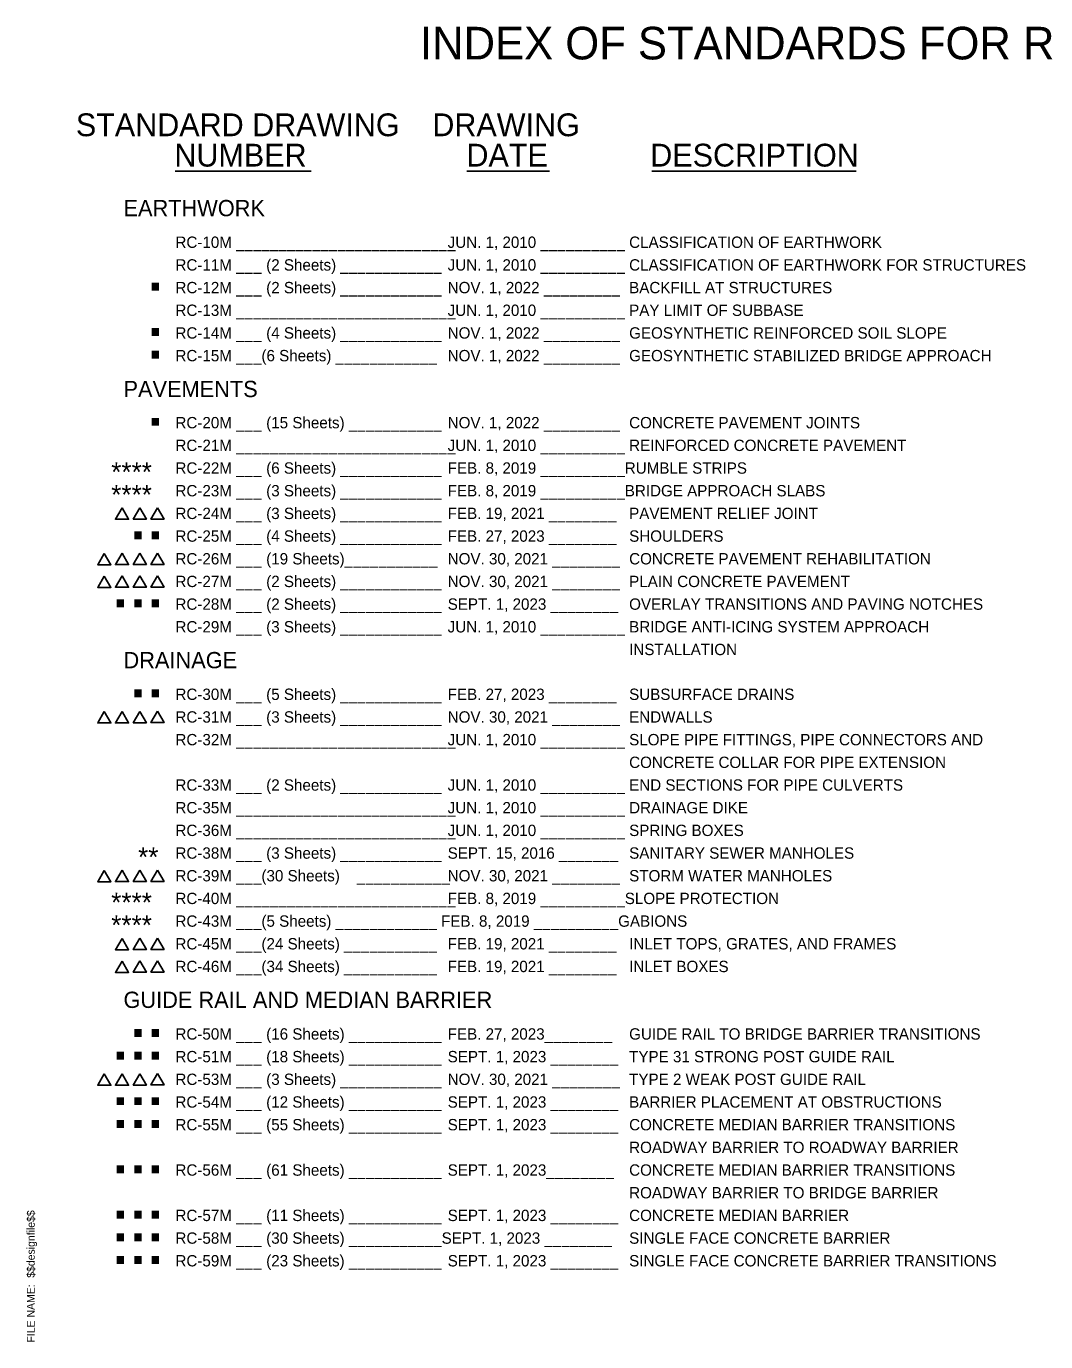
# Model space of a CAD drawing. Extents: x 0.08 to 2.68, y 0.04 to 1.72.
# Drawn here: x 0.084 to 1.387, y 0.043 to 1.725 of the extents above; entities that cross this region are included whole.
import ezdxf

# ---------------------------------------------------------------- set-up
doc = ezdxf.new("R2010")
doc.units = 0
doc.layers.add('Default', color=7, linetype='Continuous')
doc.layers.add('PLT-BNDY', color=7, linetype='Continuous')

msp = doc.modelspace()

# ---------------------------------------------------------------- linework, layer by layer
at = {"layer": 'PLT-BNDY'}
for p, q in [((0.2747, 1.5393), (0.4485, 1.5393)), ((0.6473, 1.5393), (0.7532, 1.5393)), ((0.8841, 1.5393), (1.1451, 1.5393))]:
    msp.add_line(p, q, dxfattribs=at)
for points in [[(0.2066, 1.1088), (0.1982, 1.0943), (0.215, 1.0943)], [(0.2293, 1.109), (0.2209, 1.0945), (0.2377, 1.0945)], [(0.252, 1.1091), (0.2436, 1.0946), (0.2604, 1.0946)], [(0.1839, 1.0507), (0.1755, 1.0362), (0.1923, 1.0362)], [(0.2066, 1.0508), (0.1982, 1.0363), (0.215, 1.0363)], [(0.2293, 1.051), (0.2209, 1.0365), (0.2377, 1.0365)], [(0.252, 1.0511), (0.2436, 1.0366), (0.2604, 1.0366)], [(0.1839, 1.0217), (0.1755, 1.0072), (0.1923, 1.0072)], [(0.2066, 1.0218), (0.1982, 1.0073), (0.215, 1.0073)], [(0.2293, 1.022), (0.2209, 1.0075), (0.2377, 1.0075)], [(0.252, 1.0221), (0.2436, 1.0076), (0.2604, 1.0076)], [(0.1839, 0.8484), (0.1755, 0.8339), (0.1923, 0.8339)], [(0.2066, 0.8485), (0.1982, 0.834), (0.215, 0.834)], [(0.2293, 0.8487), (0.2209, 0.8342), (0.2377, 0.8342)], [(0.252, 0.8488), (0.2436, 0.8343), (0.2604, 0.8343)], [(0.1839, 0.6454), (0.1755, 0.6309), (0.1923, 0.6309)], [(0.2066, 0.6455), (0.1982, 0.631), (0.215, 0.631)], [(0.2293, 0.6457), (0.2209, 0.6312), (0.2377, 0.6312)], [(0.252, 0.6458), (0.2436, 0.6313), (0.2604, 0.6313)], [(0.2066, 0.5585), (0.1982, 0.544), (0.215, 0.544)], [(0.2293, 0.5587), (0.2209, 0.5442), (0.2377, 0.5442)], [(0.252, 0.5588), (0.2436, 0.5443), (0.2604, 0.5443)], [(0.2066, 0.5295), (0.1982, 0.515), (0.215, 0.515)], [(0.2293, 0.5297), (0.2209, 0.5152), (0.2377, 0.5152)], [(0.252, 0.5298), (0.2436, 0.5153), (0.2604, 0.5153)], [(0.1839, 0.3851), (0.1755, 0.3706), (0.1923, 0.3706)], [(0.2066, 0.3852), (0.1982, 0.3707), (0.215, 0.3707)], [(0.2293, 0.3854), (0.2209, 0.3709), (0.2377, 0.3709)], [(0.252, 0.3855), (0.2436, 0.371), (0.2604, 0.371)]]:
    msp.add_lwpolyline(points, close=True, dxfattribs=at)

# ---------------------------------------------------------------- texts
at = {"layer": 'Default'}
for s, height, p in [('RC-10M __________________________', 0.0145, (0.2749, 1.4413)), ('JUN. 1, 2010 __________', 0.0145, (0.6229, 1.4413)), ('CLASSIFICATION OF EARTHWORK', 0.0145, (0.8549, 1.4413)), ('RC-11M ___', 0.0145, (0.2749, 1.4123)), ('(2 Sheets) ____________', 0.0145, (0.3909, 1.4123)), ('JUN. 1, 2010 __________', 0.0145, (0.6229, 1.4123)), ('CLASSIFICATION OF EARTHWORK FOR STRUCTURES', 0.0145, (0.8549, 1.4123)), ('■', 0.0145, (0.2434, 1.3853)), ('RC-12M ___', 0.0145, (0.2749, 1.3833)), ('(2 Sheets) ____________', 0.0145, (0.3909, 1.3833)), ('NOV. 1, 2022 _________', 0.0145, (0.6229, 1.3833)), ('BACKFILL AT STRUCTURES', 0.0145, (0.8549, 1.3833)), ('RC-13M __________________________', 0.0145, (0.2749, 1.3543)), ('JUN. 1, 2010 __________', 0.0145, (0.6229, 1.3543)), ('PAY LIMIT OF SUBBASE', 0.0145, (0.8549, 1.3543)), ('■', 0.0145, (0.2434, 1.3273)), ('RC-14M ___', 0.0145, (0.2749, 1.3253)), ('(4 Sheets) ____________', 0.0145, (0.3909, 1.3253)), ('NOV. 1, 2022 _________', 0.0145, (0.6229, 1.3253)), ('GEOSYNTHETIC REINFORCED SOIL SLOPE', 0.0145, (0.8549, 1.3253)), ('■', 0.0145, (0.2434, 1.2983)), ('RC-15M ___(6 Sheets) ____________', 0.0145, (0.2749, 1.2963)), ('NOV. 1, 2022 _________', 0.0145, (0.6229, 1.2963)), ('GEOSYNTHETIC STABILIZED BRIDGE APPROACH', 0.0145, (0.8549, 1.2963)), ('PAVEMENTS', 0.0208, (0.2085, 1.2505)), ('■', 0.0145, (0.2434, 1.2126)), ('■', 0.0145, (0.221, 1.0676)), ('■', 0.0145, (0.2434, 1.0676)), ('■', 0.0145, (0.1985, 0.9806)), ('■', 0.0145, (0.221, 0.9806)), ('■', 0.0145, (0.2434, 0.9806)), ('■', 0.0145, (0.221, 0.8653)), ('■', 0.0145, (0.2434, 0.8653)), ('RC-30M ___', 0.0145, (0.2749, 0.8633)), ('(5 Sheets) ____________', 0.0145, (0.3909, 0.8633)), ('FEB. 27, 2023 ________', 0.0145, (0.6229, 0.8633)), ('SUBSURFACE DRAINS', 0.0145, (0.8549, 0.8633)), ('RC-31M ___', 0.0145, (0.2749, 0.8343)), ('(3 Sheets) ____________', 0.0145, (0.3909, 0.8343)), ('NOV. 30, 2021 ________', 0.0145, (0.6229, 0.8343)), ('ENDWALLS', 0.0145, (0.8549, 0.8343)), ('RC-32M __________________________', 0.0145, (0.2749, 0.8053)), ('JUN. 1, 2010 __________', 0.0145, (0.6229, 0.8053)), ('SLOPE PIPE FITTINGS, PIPE CONNECTORS AND', 0.0145, (0.8549, 0.8053)), ('CONCRETE COLLAR FOR PIPE EXTENSION', 0.0145, (0.8549, 0.7763)), ('RC-33M ___', 0.0145, (0.2749, 0.7473)), ('(2 Sheets) ____________', 0.0145, (0.3909, 0.7473)), ('JUN. 1, 2010 __________', 0.0145, (0.6229, 0.7473)), ('END SECTIONS FOR PIPE CULVERTS', 0.0145, (0.8549, 0.7473)), ('RC-35M __________________________', 0.0145, (0.2749, 0.7183)), ('JUN. 1, 2010 __________', 0.0145, (0.6229, 0.7183)), ('DRAINAGE DIKE', 0.0145, (0.8549, 0.7183)), ('RC-36M __________________________', 0.0145, (0.2749, 0.6893)), ('JUN. 1, 2010 __________', 0.0145, (0.6229, 0.6893)), ('SPRING BOXES', 0.0145, (0.8549, 0.6893)), ('RC-38M ___', 0.0145, (0.2749, 0.6603)), ('(3 Sheets) ____________', 0.0145, (0.3909, 0.6603)), ('SEPT. 15, 2016 _______', 0.0145, (0.6229, 0.6603)), ('SANITARY SEWER MANHOLES', 0.0145, (0.8549, 0.6603)), ('RC-39M ___(30 Sheets)', 0.0145, (0.2749, 0.6313)), ('NOV. 30, 2021 ________', 0.0145, (0.6229, 0.6313)), ('STORM WATER MANHOLES', 0.0145, (0.8549, 0.6313)), ('___________', 0.0145, (0.5069, 0.6313)), ('RC-40M __________________________', 0.0145, (0.2749, 0.6023)), ('FEB. 8, 2019 __________SLOPE PROTECTION', 0.0145, (0.6229, 0.6023)), ('RC-43M ___(5 Sheets) ____________ FEB. 8, 2019 __________GABIONS', 0.0145, (0.2749, 0.5733)), ('RC-45M ___(24 Sheets) ___________', 0.0145, (0.2749, 0.5443)), ('FEB. 19, 2021 ________', 0.0145, (0.6229, 0.5443)), ('INLET TOPS, GRATES, AND FRAMES', 0.0145, (0.8549, 0.5443)), ('RC-46M ___(34 Sheets) ___________', 0.0145, (0.2749, 0.5153)), ('FEB. 19, 2021 ________', 0.0145, (0.6229, 0.5153)), ('INLET BOXES', 0.0145, (0.8549, 0.5153)), ('■', 0.0145, (0.221, 0.431)), ('■', 0.0145, (0.2434, 0.431)), ('RC-50M ___', 0.0145, (0.2749, 0.429)), ('(16 Sheets) ___________', 0.0145, (0.3909, 0.429)), ('FEB. 27, 2023________', 0.0145, (0.6229, 0.429)), ('GUIDE RAIL TO BRIDGE BARRIER TRANSITIONS', 0.0145, (0.8549, 0.429)), ('■', 0.0145, (0.1985, 0.402)), ('■', 0.0145, (0.221, 0.402)), ('■', 0.0145, (0.2434, 0.402)), ('RC-51M ___', 0.0145, (0.2749, 0.4)), ('(18 Sheets) ___________', 0.0145, (0.3909, 0.4)), ('SEPT. 1, 2023 ________', 0.0145, (0.6229, 0.4)), ('TYPE 31 STRONG POST GUIDE RAIL', 0.0145, (0.8549, 0.4)), ('RC-53M ___', 0.0145, (0.2749, 0.371)), ('(3 Sheets) ____________', 0.0145, (0.3909, 0.371)), ('NOV. 30, 2021 ________', 0.0145, (0.6229, 0.371)), ('TYPE 2 WEAK POST GUIDE RAIL', 0.0145, (0.8549, 0.371)), ('■', 0.0145, (0.1985, 0.344)), ('■', 0.0145, (0.221, 0.344)), ('■', 0.0145, (0.2434, 0.344)), ('RC-54M ___', 0.0145, (0.2749, 0.342)), ('(12 Sheets) ___________', 0.0145, (0.3909, 0.342)), ('SEPT. 1, 2023 ________', 0.0145, (0.6229, 0.342)), ('BARRIER PLACEMENT AT OBSTRUCTIONS', 0.0145, (0.8549, 0.342)), ('■', 0.0145, (0.1985, 0.315)), ('■', 0.0145, (0.221, 0.315)), ('■', 0.0145, (0.2434, 0.315)), ('RC-55M ___', 0.0145, (0.2749, 0.313)), ('(55 Sheets) ___________', 0.0145, (0.3909, 0.313)), ('SEPT. 1, 2023 ________', 0.0145, (0.6229, 0.313)), ('CONCRETE MEDIAN BARRIER TRANSITIONS', 0.0145, (0.8549, 0.313)), ('ROADWAY BARRIER TO ROADWAY BARRIER', 0.0145, (0.8549, 0.284)), ('RC-56M ___', 0.0145, (0.2749, 0.255)), ('(61 Sheets) ___________', 0.0145, (0.3909, 0.255)), ('SEPT. 1, 2023________', 0.0145, (0.6229, 0.255)), ('CONCRETE MEDIAN BARRIER TRANSITIONS', 0.0145, (0.8549, 0.255)), ('■', 0.0145, (0.1985, 0.257)), ('■', 0.0145, (0.221, 0.257)), ('■', 0.0145, (0.2434, 0.257)), ('ROADWAY BARRIER TO BRIDGE BARRIER', 0.0145, (0.8549, 0.226)), ('■', 0.0145, (0.1985, 0.199)), ('■', 0.0145, (0.221, 0.199)), ('■', 0.0145, (0.2434, 0.199)), ('RC-57M ___', 0.0145, (0.2749, 0.197)), ('(11 Sheets) ___________', 0.0145, (0.3909, 0.197)), ('SEPT. 1, 2023 ________', 0.0145, (0.6229, 0.197)), ('CONCRETE MEDIAN BARRIER', 0.0145, (0.8549, 0.197)), ('■', 0.0145, (0.1985, 0.17)), ('■', 0.0145, (0.221, 0.17)), ('■', 0.0145, (0.2434, 0.17)), ('RC-58M ___', 0.0145, (0.2749, 0.168)), ('(30 Sheets) ___________SEPT. 1, 2023 ________', 0.0145, (0.3909, 0.168)), ('SINGLE FACE CONCRETE BARRIER', 0.0145, (0.8549, 0.168)), ('■', 0.0145, (0.1985, 0.141)), ('■', 0.0145, (0.221, 0.141)), ('■', 0.0145, (0.2434, 0.141)), ('RC-59M ___', 0.0145, (0.2749, 0.139)), ('(23 Sheets) ___________', 0.0145, (0.3909, 0.139)), ('SEPT. 1, 2023 ________', 0.0145, (0.6229, 0.139)), ('SINGLE FACE CONCRETE BARRIER TRANSITIONS', 0.0145, (0.8549, 0.139))]:
    msp.add_text(s, height=height, dxfattribs=at).set_placement(p)
for s, p in [('$$designfile$$', (0.095, 0.1245)), ('FILE NAME:', (0.095, 0.0417))]:
    msp.add_text(s, height=0.01, rotation=90, dxfattribs=at).set_placement(p)
at = {"layer": 'PLT-BNDY'}
for s, height, p in [('INDEX OF STANDARDS FOR ROADWAY CONSTRUCTION', 0.041667, (0.5875, 1.6823)), ('STANDARD DRAWING', 0.029167, (0.1476, 1.5841)), ('DRAWING', 0.02917, (0.6033, 1.5841)), ('NUMBER', 0.02917, (0.2735, 1.5453)), ('DATE', 0.02917, (0.6469, 1.5453)), ('DESCRIPTION', 0.029167, (0.8819, 1.5453)), ('EARTHWORK', 0.0208, (0.2085, 1.4818)), ('RC-20M ___', 0.0145, (0.2749, 1.2106)), ('(15 Sheets) ___________', 0.0145, (0.3909, 1.2106)), ('NOV. 1, 2022 _________', 0.0145, (0.6229, 1.2106)), ('CONCRETE PAVEMENT JOINTS', 0.0145, (0.8549, 1.2106)), ('RC-21M __________________________', 0.0145, (0.2749, 1.1816)), ('JUN. 1, 2010 __________', 0.0145, (0.6229, 1.1816)), ('REINFORCED CONCRETE PAVEMENT', 0.0145, (0.8549, 1.1816)), ('****', 0.025, (0.1928, 1.1423)), ('RC-22M ___', 0.0145, (0.2749, 1.1526)), ('(6 Sheets) ____________', 0.0145, (0.3909, 1.1526)), ('FEB. 8, 2019 __________RUMBLE STRIPS', 0.0145, (0.6229, 1.1526)), ('****', 0.025, (0.1928, 1.1133)), ('RC-23M ___', 0.0145, (0.2749, 1.1236)), ('(3 Sheets) ____________', 0.0145, (0.3909, 1.1236)), ('FEB. 8, 2019 __________BRIDGE APPROACH SLABS', 0.0145, (0.6229, 1.1236)), ('RC-24M ___', 0.0145, (0.2749, 1.0946)), ('(3 Sheets) ____________', 0.0145, (0.3909, 1.0946)), ('FEB. 19, 2021 ________', 0.0145, (0.6229, 1.0946)), ('PAVEMENT RELIEF JOINT', 0.0145, (0.8549, 1.0946)), ('RC-25M ___', 0.0145, (0.2749, 1.0656)), ('(4 Sheets) ____________', 0.0145, (0.3909, 1.0656)), ('FEB. 27, 2023 ________', 0.0145, (0.6229, 1.0656)), ('SHOULDERS', 0.0145, (0.8549, 1.0656)), ('RC-26M ___', 0.0145, (0.2749, 1.0366)), ('(19 Sheets)___________', 0.0145, (0.3909, 1.0366)), ('NOV. 30, 2021 ________', 0.0145, (0.6229, 1.0366)), ('CONCRETE PAVEMENT REHABILITATION', 0.0145, (0.8549, 1.0366)), ('RC-27M ___', 0.0145, (0.2749, 1.0076)), ('(2 Sheets) ____________', 0.0145, (0.3909, 1.0076)), ('NOV. 30, 2021 ________', 0.0145, (0.6229, 1.0076)), ('PLAIN CONCRETE PAVEMENT', 0.0145, (0.8549, 1.0076)), ('RC-28M ___', 0.0145, (0.2749, 0.9786)), ('(2 Sheets) ____________', 0.0145, (0.3909, 0.9786)), ('SEPT. 1, 2023 ________', 0.0145, (0.6229, 0.9786)), ('OVERLAY TRANSITIONS AND PAVING NOTCHES', 0.0145, (0.8549, 0.9786)), ('RC-29M ___', 0.0145, (0.2749, 0.9496)), ('(3 Sheets) ____________', 0.0145, (0.3909, 0.9496)), ('JUN. 1, 2010 __________', 0.0145, (0.6229, 0.9496)), ('BRIDGE ANTI-ICING SYSTEM APPROACH', 0.0145, (0.8549, 0.9496)), ('INSTALLATION', 0.0145, (0.8549, 0.9206)), ('DRAINAGE', 0.0208, (0.2085, 0.9038)), ('**', 0.025, (0.2271, 0.65)), ('****', 0.025, (0.1928, 0.592)), ('****', 0.025, (0.1928, 0.563)), ('GUIDE RAIL AND MEDIAN BARRIER', 0.0208, (0.2085, 0.4695))]:
    msp.add_text(s, height=height, dxfattribs=at).set_placement(p)

doc.saveas('drawing.dxf')
